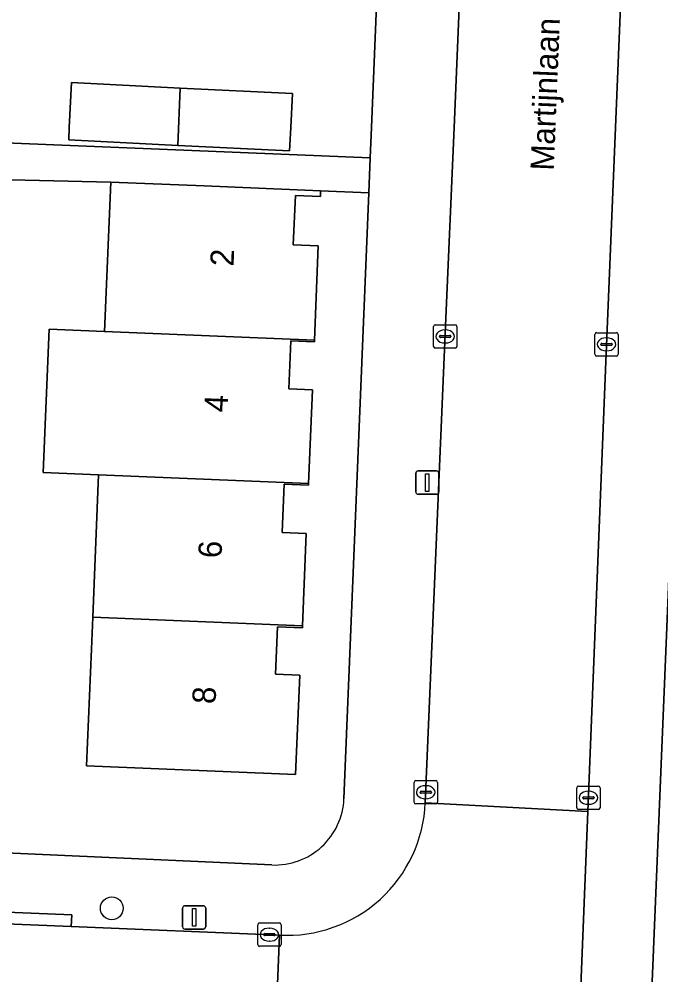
# Model space of a CAD drawing. Extents: x 160077 to 160948, y 386481 to 387498.
# Drawn here: x 160595.16 to 160622.65, y 386713.69 to 386754.65 of the extents above; entities that cross this region are included whole.
import ezdxf

# ---------------------------------------------------------------- set-up
doc = ezdxf.new("R2010")
doc.units = 0
for name, color, linetype in [('IMGEO_Boom', 7, 'Continuous'), ('IMGEO_Erf', 7, 'Continuous'), ('IMGEO_Kolk', 7, 'Continuous'), ('IMGEO_Lichtmast', 7, 'Continuous'), ('IMGEO_Openbare_ruimte_label', 7, 'Continuous'), ('IMGEO_Pand', 7, 'Continuous'), ('IMGEO_Pand_nummerreeks', 7, 'Continuous'), ('IMGEO_Rijbaan_lokaal_open', 7, 'Continuous'), ('IMGEO_Voetpad_open', 7, 'Continuous')]:
    doc.layers.add(name, color=color, linetype=linetype)

msp = doc.modelspace()

# ---------------------------------------------------------------- linework, layer by layer
at = {"layer": 'IMGEO_Boom'}
msp.add_circle((160599.132, 386716.546), 0.489, dxfattribs=at)
at = {"layer": 'IMGEO_Erf'}
for points in [[(160583.725, 386755.652), (160583.585, 386752.723), (160583.446, 386749.795), (160610.202, 386748.699), (160610.255, 386750), (160611.199, 386773.064)], [(160623.787, 386750), (160621.452, 386693.374), (160627.397, 386693.129)], [(160610.141, 386747.206), (160608.077, 386747.291), (160608.067, 386747.046), (160606.994, 386747.091), (160606.906, 386744.971), (160607.977, 386744.927), (160607.811, 386740.892), (160607.808, 386740.82), (160606.797, 386740.862), (160606.712, 386738.801), (160607.723, 386738.76), (160607.557, 386734.753), (160607.554, 386734.681), (160606.512, 386734.724), (160606.426, 386732.654), (160607.464, 386732.611), (160607.301, 386728.65), (160607.297, 386728.56), (160606.231, 386728.604), (160606.148, 386726.581), (160607.179, 386726.538), (160607.003, 386722.283), (160598.051, 386722.652), (160598.257, 386727.648), (160598.314, 386729.018), (160598.565, 386735.122), (160596.197, 386735.22), (160596.451, 386741.358), (160598.819, 386741.26), (160599.083, 386747.662), (160589.29, 386747.881)], [(160609.077, 386721.242), (160610.141, 386747.206)], [(160588.239, 386719.208), (160605.982, 386718.402)]]:
    msp.add_lwpolyline(points, dxfattribs=at)
msp.add_lwpolyline([(160602.067, 386751.694), (160606.872, 386751.456), (160606.8, 386750), (160606.75, 386749), (160601.961, 386749.237), (160597.284, 386749.468), (160597.31, 386750), (160597.406, 386751.924)], close=True, dxfattribs=at)
msp.add_arc((160606.113, 386721.365), 2.966, 267.4639, 357.6157, dxfattribs=at)
at = {"layer": 'IMGEO_Kolk'}
for p, q in [((160612.911, 386740.623), (160612.911, 386741.475)), ((160612.986, 386741.549), (160613.838, 386741.549)), ((160613.912, 386741.475), (160613.912, 386740.623)), ((160613.17, 386741.043), (160613.17, 386741.055)), ((160613.608, 386741.006), (160613.21, 386741.006)), ((160613.213, 386741.092), (160613.611, 386741.092)), ((160613.399, 386741.329), (160613.424, 386741.329)), ((160613.654, 386741.055), (160613.654, 386741.043)), ((160619.823, 386740.284), (160619.823, 386741.136)), ((160619.898, 386741.21), (160620.75, 386741.21)), ((160620.311, 386740.99), (160620.336, 386740.99)), ((160620.824, 386741.136), (160620.824, 386740.284)), ((160613.422, 386740.769), (160613.397, 386740.769)), ((160620.082, 386740.704), (160620.082, 386740.716)), ((160620.52, 386740.667), (160620.122, 386740.667)), ((160620.125, 386740.753), (160620.523, 386740.753)), ((160620.566, 386740.716), (160620.566, 386740.704)), ((160613.838, 386740.549), (160612.986, 386740.549)), ((160620.75, 386740.21), (160619.898, 386740.21)), ((160620.334, 386740.43), (160620.309, 386740.43)), ((160612.078, 386721.09), (160612.078, 386721.942)), ((160612.153, 386722.016), (160613.005, 386722.016)), ((160612.566, 386721.796), (160612.591, 386721.796)), ((160613.079, 386721.942), (160613.079, 386721.09)), ((160619.123, 386721.78), (160619.975, 386721.78)), ((160612.337, 386721.51), (160612.337, 386721.522)), ((160612.775, 386721.473), (160612.377, 386721.473)), ((160612.38, 386721.559), (160612.778, 386721.559)), ((160612.821, 386721.522), (160612.821, 386721.51)), ((160619.048, 386720.854), (160619.048, 386721.706)), ((160619.536, 386721.56), (160619.561, 386721.56)), ((160620.049, 386721.706), (160620.049, 386720.854)), ((160613.005, 386721.016), (160612.153, 386721.016)), ((160612.589, 386721.236), (160612.564, 386721.236)), ((160619.307, 386721.274), (160619.307, 386721.286)), ((160619.745, 386721.237), (160619.347, 386721.237)), ((160619.35, 386721.323), (160619.748, 386721.323)), ((160619.559, 386721), (160619.534, 386721)), ((160619.791, 386721.286), (160619.791, 386721.274)), ((160619.975, 386720.78), (160619.123, 386720.78)), ((160605.382, 386714.989), (160605.382, 386715.841)), ((160605.457, 386715.915), (160606.309, 386715.915)), ((160605.87, 386715.695), (160605.895, 386715.695)), ((160606.383, 386715.841), (160606.383, 386714.989)), ((160605.641, 386715.409), (160605.641, 386715.421)), ((160606.079, 386715.372), (160605.681, 386715.372)), ((160605.684, 386715.458), (160606.082, 386715.458)), ((160606.125, 386715.421), (160606.125, 386715.409)), ((160606.309, 386714.915), (160605.457, 386714.915)), ((160605.893, 386715.135), (160605.868, 386715.135))]:
    msp.add_line(p, q, dxfattribs=at)
for points in [[(160612.911, 386740.623), (160612.911, 386741.475)], [(160612.986, 386741.549), (160613.838, 386741.549)], [(160613.912, 386741.475), (160613.912, 386740.623)], [(160619.823, 386740.284), (160619.823, 386741.136)], [(160619.898, 386741.21), (160620.75, 386741.21)], [(160620.824, 386741.136), (160620.824, 386740.284)], [(160613.838, 386740.549), (160612.986, 386740.549)], [(160620.75, 386740.21), (160619.898, 386740.21)], [(160612.078, 386721.09), (160612.078, 386721.942)], [(160612.153, 386722.016), (160613.005, 386722.016)], [(160613.079, 386721.942), (160613.079, 386721.09)], [(160619.123, 386721.78), (160619.975, 386721.78)], [(160619.048, 386720.854), (160619.048, 386721.706)], [(160620.049, 386721.706), (160620.049, 386720.854)], [(160613.005, 386721.016), (160612.153, 386721.016)], [(160619.975, 386720.78), (160619.123, 386720.78)], [(160605.382, 386714.989), (160605.382, 386715.841)], [(160605.457, 386715.915), (160606.309, 386715.915)], [(160606.383, 386715.841), (160606.383, 386714.989)], [(160606.309, 386714.915), (160605.457, 386714.915)]]:
    msp.add_lwpolyline(points, dxfattribs=at)
for centre, radius, start, end in [((160612.988, 386741.473), 0.0765, 91.552, 178.448), ((160612.988, 386741.473), 0.0765, 91.552, 178.448), ((160613.836, 386741.473), 0.0765, 1.552, 88.448), ((160613.836, 386741.473), 0.0765, 1.552, 88.448), ((160613.21, 386741.052), 0.0403, 85.8775, 175.7526), ((160613.207, 386741.042), 0.0366, 178.938, 274.7102), ((160613.611, 386741.049), 0.043, 264.8664, 352.4533), ((160613.615, 386741.054), 0.0386, 1.7309, 96.639), ((160619.9, 386741.134), 0.0765, 91.552, 178.448), ((160619.9, 386741.134), 0.0765, 91.552, 178.448), ((160620.748, 386741.134), 0.0765, 1.552, 88.448), ((160620.748, 386741.134), 0.0765, 1.552, 88.448), ((160612.988, 386740.625), 0.0765, 181.552, 268.448), ((160612.988, 386740.625), 0.0765, 181.552, 268.448), ((160613.836, 386740.625), 0.0765, 271.552, 358.448), ((160613.836, 386740.625), 0.0765, 271.552, 358.448), ((160620.122, 386740.713), 0.0403, 85.8775, 175.7526), ((160620.119, 386740.703), 0.0366, 178.938, 274.7102), ((160620.523, 386740.71), 0.043, 264.8664, 352.4533), ((160620.527, 386740.715), 0.0386, 1.7309, 96.639), ((160619.9, 386740.286), 0.0765, 181.552, 268.448), ((160619.9, 386740.286), 0.0765, 181.552, 268.448), ((160620.748, 386740.286), 0.0765, 271.552, 358.448), ((160620.748, 386740.286), 0.0765, 271.552, 358.448), ((160612.155, 386721.94), 0.0765, 91.552, 178.448), ((160612.155, 386721.94), 0.0765, 91.552, 178.448), ((160613.003, 386721.94), 0.0765, 1.552, 88.448), ((160613.003, 386721.94), 0.0765, 1.552, 88.448), ((160619.125, 386721.704), 0.0765, 91.552, 178.448), ((160619.125, 386721.704), 0.0765, 91.552, 178.448), ((160619.973, 386721.704), 0.0765, 1.552, 88.448), ((160619.973, 386721.704), 0.0765, 1.552, 88.448), ((160612.377, 386721.519), 0.0403, 85.8775, 175.7526), ((160612.374, 386721.509), 0.0366, 178.938, 274.7102), ((160612.778, 386721.516), 0.043, 264.8664, 352.4533), ((160612.782, 386721.521), 0.0386, 1.7309, 96.639), ((160612.155, 386721.092), 0.0765, 181.552, 268.448), ((160612.155, 386721.092), 0.0765, 181.552, 268.448), ((160613.003, 386721.092), 0.0765, 271.552, 358.448), ((160613.003, 386721.092), 0.0765, 271.552, 358.448), ((160619.347, 386721.283), 0.0403, 85.8775, 175.7526), ((160619.344, 386721.273), 0.0366, 178.938, 274.7102), ((160619.748, 386721.28), 0.043, 264.8664, 352.4533), ((160619.752, 386721.285), 0.0386, 1.7309, 96.639), ((160619.125, 386720.856), 0.0765, 181.552, 268.448), ((160619.125, 386720.856), 0.0765, 181.552, 268.448), ((160619.973, 386720.856), 0.0765, 271.552, 358.448), ((160619.973, 386720.856), 0.0765, 271.552, 358.448), ((160605.459, 386715.839), 0.0765, 91.552, 178.448), ((160605.459, 386715.839), 0.0765, 91.552, 178.448), ((160606.307, 386715.839), 0.0765, 1.552, 88.448), ((160606.307, 386715.839), 0.0765, 1.552, 88.448), ((160605.681, 386715.418), 0.0403, 85.8775, 175.7526), ((160605.678, 386715.408), 0.0366, 178.938, 274.7102), ((160606.082, 386715.415), 0.043, 264.8664, 352.4533), ((160606.086, 386715.42), 0.0386, 1.7309, 96.639), ((160605.459, 386714.991), 0.0765, 181.552, 268.448), ((160605.459, 386714.991), 0.0765, 181.552, 268.448), ((160606.307, 386714.991), 0.0765, 271.552, 358.448), ((160606.307, 386714.991), 0.0765, 271.552, 358.448)]:
    msp.add_arc(centre, radius, start, end, dxfattribs=at)
for centre, major_axis, ratio, start_param, end_param in [((160613.398, 386741.049), (-0.387, 0.002), 0.722429, 4.712389, 7.853982), ((160613.423, 386741.049), (-0.39, 0.002), 0.717154, 1.570796, 4.712389), ((160620.31, 386740.71), (-0.387, 0.002), 0.722429, 4.712389, 7.853982), ((160620.335, 386740.71), (-0.39, 0.002), 0.717154, 1.570796, 4.712389), ((160612.565, 386721.516), (-0.387, 0.002), 0.722429, 4.712389, 7.853982), ((160612.59, 386721.516), (-0.39, 0.002), 0.717154, 1.570796, 4.712389), ((160619.535, 386721.28), (-0.387, 0.002), 0.722429, 4.712389, 7.853982), ((160619.56, 386721.28), (-0.39, 0.002), 0.717154, 1.570796, 4.712389), ((160605.869, 386715.415), (-0.387, 0.002), 0.722429, 4.712389, 7.853982), ((160605.894, 386715.415), (-0.39, 0.002), 0.717154, 1.570796, 4.712389)]:
    msp.add_ellipse(centre, major_axis=major_axis, ratio=ratio, start_param=start_param, end_param=end_param, dxfattribs=at)
at = {"layer": 'IMGEO_Lichtmast'}
for p, q in [((160612.249, 386735.285), (160613.039, 386735.285)), ((160613.039, 386735.285), (160612.249, 386735.285)), ((160612.149, 386734.385), (160612.149, 386735.185)), ((160612.149, 386735.185), (160612.149, 386734.385)), ((160613.139, 386735.185), (160613.139, 386734.385)), ((160613.139, 386734.385), (160613.139, 386735.185)), ((160613.039, 386734.285), (160612.249, 386734.285)), ((160612.249, 386734.285), (160613.039, 386734.285)), ((160602.163, 386715.756), (160602.163, 386716.556)), ((160602.163, 386716.556), (160602.163, 386715.756)), ((160602.263, 386716.656), (160603.053, 386716.656)), ((160603.053, 386716.656), (160602.263, 386716.656)), ((160603.153, 386716.556), (160603.153, 386715.756)), ((160603.153, 386715.756), (160603.153, 386716.556)), ((160603.053, 386715.656), (160602.263, 386715.656)), ((160602.263, 386715.656), (160603.053, 386715.656))]:
    msp.add_line(p, q, dxfattribs=at)
for points in [[(160612.569, 386735.16), (160612.719, 386735.16), (160612.719, 386734.41), (160612.569, 386734.41), (160612.569, 386735.16)], [(160602.583, 386716.531), (160602.733, 386716.531), (160602.733, 386715.781), (160602.583, 386715.781), (160602.583, 386716.531)]]:
    msp.add_lwpolyline(points, dxfattribs=at)
for centre, start, end in [((160612.249, 386735.185), 90, 180), ((160612.249, 386735.185), 90, 180), ((160613.039, 386735.185), 0, 90), ((160613.039, 386735.185), 360, 90), ((160612.249, 386734.385), 180, 270), ((160612.249, 386734.385), 180, 270), ((160613.039, 386734.385), 270, 0), ((160613.039, 386734.385), 270, 0), ((160602.263, 386716.556), 90, 180), ((160602.263, 386716.556), 90, 180), ((160603.053, 386716.556), 0, 90), ((160603.053, 386716.556), 360, 90), ((160602.263, 386715.756), 180, 270), ((160602.263, 386715.756), 180, 270), ((160603.053, 386715.756), 270, 0), ((160603.053, 386715.756), 270, 0)]:
    msp.add_arc(centre, 0.1, start, end, dxfattribs=at)
at = {"layer": 'IMGEO_Pand'}
for points in [[(160602.067, 386751.694), (160597.406, 386751.924), (160597.31, 386750), (160597.284, 386749.468), (160601.961, 386749.237)], [(160601.961, 386749.237), (160606.75, 386749), (160606.8, 386750), (160606.872, 386751.456), (160602.067, 386751.694)], [(160607.811, 386740.892), (160607.977, 386744.927), (160606.906, 386744.971), (160606.994, 386747.091), (160608.067, 386747.046), (160608.077, 386747.291), (160603.082, 386747.497), (160599.083, 386747.662), (160598.819, 386741.26)], [(160607.723, 386738.76), (160606.712, 386738.801), (160606.797, 386740.862), (160607.808, 386740.82), (160607.811, 386740.892), (160598.819, 386741.26), (160596.451, 386741.358), (160596.197, 386735.22), (160598.565, 386735.122), (160607.557, 386734.753)], [(160606.426, 386732.654), (160606.512, 386734.724), (160607.554, 386734.681), (160607.557, 386734.753), (160598.565, 386735.122), (160598.314, 386729.018), (160607.301, 386728.65), (160607.464, 386732.611)], [(160606.231, 386728.604), (160607.297, 386728.56), (160607.301, 386728.65), (160598.314, 386729.018), (160598.257, 386727.648), (160598.051, 386722.652), (160607.003, 386722.283), (160607.179, 386726.538), (160606.148, 386726.581)]]:
    msp.add_lwpolyline(points, close=True, dxfattribs=at)
at = {"layer": 'IMGEO_Rijbaan_lokaal_open'}
msp.add_lwpolyline([(160621.661, 386773.193), (160614.688, 386772.962), (160614.299, 386761.99), (160613.792, 386750), (160613.446, 386741.825), (160612.561, 386721.068), (160619.524, 386720.686), (160620.278, 386739.623), (160620.706, 386750)], close=True, dxfattribs=at)
for points in [[(160619.524, 386720.686), (160612.561, 386721.068)], [(160611.777, 386702.444), (160618.787, 386702.164), (160619.524, 386720.686)], [(160606.312, 386715.396), (160597.395, 386715.765), (160593.538, 386715.924), (160591.679, 386716.001), (160568.768, 386717.052), (160566.885, 386717.053), (160565.023, 386716.883), (160563.183, 386716.548), (160562.052, 386716.255)], [(160568.739, 386709.981), (160586.668, 386709.162), (160606.031, 386708.388), (160606.312, 386715.396)], [(160606.312, 386715.396), (160606.031, 386708.388), (160606.255, 386708.379)]]:
    msp.add_lwpolyline(points, dxfattribs=at)
msp.add_arc((160606.634, 386721.32), 5.933, 266.8916, 357.5662, dxfattribs=at)
at = {"layer": 'IMGEO_Voetpad_open'}
for points in [[(160621.394, 386691.978), (160621.423, 386692.671), (160621.452, 386693.374), (160623.787, 386750), (160624.002, 386755.214), (160624.053, 386756.457), (160624.696, 386772.042), (160624.671, 386772.055), (160624.977, 386777.704)], [(160614.688, 386772.962), (160611.199, 386773.064), (160610.255, 386750), (160610.202, 386748.699), (160610.141, 386747.206), (160609.077, 386721.242)], [(160612.561, 386721.068), (160613.446, 386741.825), (160613.792, 386750), (160614.299, 386761.99), (160614.688, 386772.962)], [(160621.661, 386773.193), (160620.706, 386750), (160620.278, 386739.623), (160619.524, 386720.686), (160618.787, 386702.164), (160618.548, 386696.166), (160617.271, 386665.941), (160616.069, 386637.291), (160615.656, 386623.956)], [(160589.29, 386747.881), (160599.083, 386747.662), (160603.082, 386747.497), (160608.077, 386747.291), (160610.141, 386747.206), (160610.202, 386748.699), (160583.446, 386749.795)], [(160605.982, 386718.402), (160588.239, 386719.208), (160586.575, 386719.284), (160567.893, 386720.133)], [(160562.052, 386716.255), (160561.874, 386716.723), (160563.165, 386717.057), (160565.028, 386717.389), (160566.913, 386717.554), (160566.885, 386717.053), (160568.768, 386717.052), (160591.679, 386716.001), (160593.538, 386715.924), (160593.559, 386716.423), (160597.416, 386716.264), (160597.395, 386715.765), (160606.312, 386715.396)]]:
    msp.add_lwpolyline(points, dxfattribs=at)
msp.add_lwpolyline([(160593.538, 386715.924), (160597.395, 386715.765), (160597.416, 386716.264), (160593.559, 386716.423)], close=True, dxfattribs=at)
for centre, radius, start, end in [((160606.113, 386721.365), 2.966, 267.4639, 357.6157), ((160606.634, 386721.32), 5.933, 266.8916, 357.5662)]:
    msp.add_arc(centre, radius, start, end, dxfattribs=at)

# ---------------------------------------------------------------- texts
at = {"layer": 'IMGEO_Openbare_ruimte_label'}
msp.add_text('Martijnlaan', height=1, rotation=87.6498, dxfattribs=at).set_placement((160618.06, 386748.14))
at = {"layer": 'IMGEO_Pand_nummerreeks'}
for s, rotation, p in [('2', 87.64, (160604.346, 386744.036)), ('4', 87.6396, (160604.088, 386737.785)), ('6', 87.6396, (160603.83, 386731.533)), ('8', 87.6396, (160603.574, 386725.284))]:
    msp.add_text(s, height=1, rotation=rotation, dxfattribs=at).set_placement(p)

doc.saveas('drawing.dxf')
